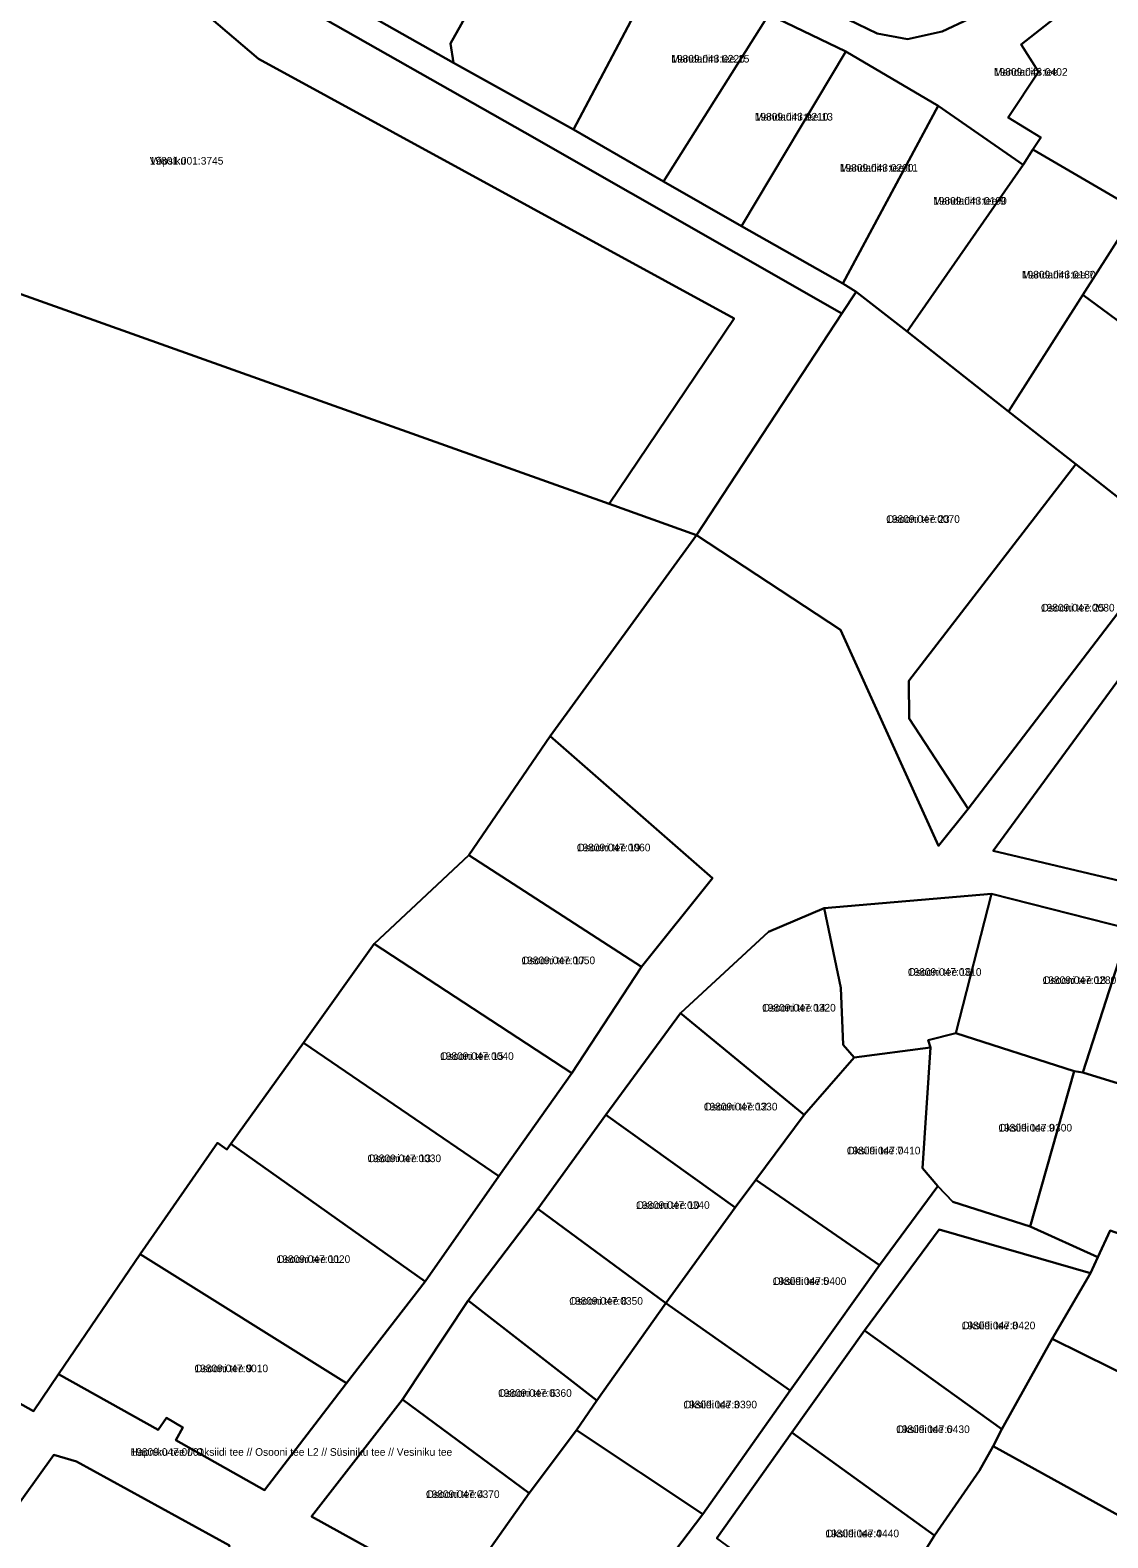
# Model space of a CAD drawing. Extents: x 516875 to 535633, y 6574491 to 6593094.
# Drawn here: x 521809.5 to 522021.7, y 6588097.9 to 6588394.7 of the extents above; entities that cross this region are included whole.
import ezdxf

# ---------------------------------------------------------------- set-up
doc = ezdxf.new("R2010")
doc.units = 0
for name, color, linetype in [('L_AADRESS', 7, 'Continuous'), ('PIIR', 7, 'Continuous'), ('TUNNUS', 7, 'Continuous')]:
    doc.layers.add(name, color=color, linetype=linetype)

msp = doc.modelspace()

# ---------------------------------------------------------------- linework, layer by layer
at = {"layer": 'PIIR'}
for points in [[(521900.47, 6588438.26), (521914.21, 6588425.95), (521901.23, 6588408.16), (521892.23, 6588392.11), (521892.86, 6588388.28), (521865.08, 6588404.07)], [(521767.83, 6588356.93), (521806.88, 6588434.72), (521807.21, 6588435.06), (521811.68, 6588425.58), (521854.43, 6588389.09), (521948.1, 6588337.93), (521923.51, 6588301.46)], [(521976.23, 6588394.06), (521970.55, 6588396.81), (521974.86, 6588399.29), (521966.52, 6588427.38), (521989.2, 6588434.61), (522000.4, 6588405.25), (522000.86, 6588402.21), (521999.67, 6588399.47), (521989.07, 6588394.48), (521982.2, 6588392.97)], [(521892.23, 6588392.11), (521901.23, 6588408.16), (521914.21, 6588425.95), (521934.81, 6588409.94), (521916.48, 6588375.14), (521892.86, 6588388.28)], [(521916.48, 6588375.14), (521934.81, 6588409.94), (521954.92, 6588397.82), (521934.21, 6588364.92)], [(522006.88, 6588371.24), (522008.43, 6588373.57), (522002.04, 6588377.52), (522008, 6588386.5), (522004.6, 6588391.87), (522018.39, 6588402.82), (522044.38, 6588382.1), (522038.94, 6588374.15), (522028.11, 6588358.8), (522027.34, 6588359.31)], [(521934.21, 6588364.92), (521954.92, 6588397.82), (521970.07, 6588390.49), (521949.55, 6588356.12)], [(521969.5, 6588344.88), (521949.55, 6588356.12), (521970.07, 6588390.49), (521988.23, 6588379.85)], [(521969.5, 6588344.88), (521988.23, 6588379.85), (522004.99, 6588368.24), (521982.14, 6588335.38), (521972.13, 6588343.24)], [(521982.14, 6588335.38), (522004.99, 6588368.24), (522006.88, 6588371.24), (522027.34, 6588359.31), (522016.7, 6588342.59), (522002.12, 6588319.68)], [(521662.26, 6588206.2), (521660.34, 6588207.31), (521739.03, 6588351.41), (521745.91, 6588364.74), (521767.83, 6588356.93), (521923.51, 6588301.46), (521940.7, 6588295.34), (521911.84, 6588255.77), (521895.87, 6588232.3), (521877.19, 6588214.89), (521863.3, 6588195.38), (521848.98, 6588175.48), (521848.19, 6588174.37), (521846.41, 6588175.69), (521831.14, 6588153.76), (521815.1, 6588130.16), (521810.15, 6588122.86), (521677.48, 6588197.33)], [(522027.34, 6588359.31), (522028.11, 6588358.8), (522057.37, 6588337.19), (522046.97, 6588320.29), (522016.7, 6588342.59)], [(522015.34, 6588309.29), (521982.46, 6588266.63), (521982.51, 6588259.22), (521994.15, 6588241.44), (521988.31, 6588234.16), (521969.03, 6588276.66), (521940.7, 6588295.34), (521969.29, 6588338.92), (521972.13, 6588343.24), (521982.14, 6588335.38), (522002.12, 6588319.68)], [(522016.7, 6588342.59), (522046.97, 6588320.29), (522041.55, 6588311.63), (522034.49, 6588294.19), (522015.34, 6588309.29), (522002.12, 6588319.68)], [(522034.49, 6588294.19), (521994.15, 6588241.44), (521982.51, 6588259.22), (521982.46, 6588266.63), (522015.34, 6588309.29)], [(522061, 6588274.09), (522025.42, 6588226.93), (521999.1, 6588233.14), (522040.58, 6588289.75)], [(521911.84, 6588255.77), (521943.84, 6588227.81), (521929.82, 6588210.36), (521895.87, 6588232.3)], [(521929.82, 6588210.36), (521916.15, 6588189.39), (521877.19, 6588214.89), (521895.87, 6588232.3)], [(521998.77, 6588224.68), (521991.75, 6588197.28), (521986.29, 6588195.87), (521986.72, 6588194.45), (521971.74, 6588192.49), (521969.57, 6588194.99), (521969.09, 6588206.19), (521965.79, 6588221.88)], [(522025.87, 6588217.8), (522016.71, 6588189.53), (522015.02, 6588189.79), (521991.75, 6588197.28), (521998.77, 6588224.68)], [(521969.09, 6588206.19), (521969.57, 6588194.99), (521971.74, 6588192.49), (521961.88, 6588181.18), (521937.53, 6588201.19), (521954.83, 6588217.23), (521965.79, 6588221.88)], [(522049.87, 6588211.85), (522040.05, 6588182.35), (522037.62, 6588183.1), (522016.71, 6588189.53), (522025.87, 6588217.8)], [(521916.15, 6588189.39), (521901.78, 6588169.12), (521863.3, 6588195.38), (521877.19, 6588214.89)], [(521961.88, 6588181.18), (521952.34, 6588168.38), (521948.3, 6588162.93), (521922.82, 6588181.22), (521937.53, 6588201.19)], [(521991.75, 6588197.28), (522015.02, 6588189.79), (522006.38, 6588159.24), (521991.14, 6588164.07), (521988.17, 6588167.15), (521985.19, 6588170.72), (521986.72, 6588194.45), (521986.29, 6588195.87)], [(521901.78, 6588169.12), (521887.28, 6588148.38), (521848.98, 6588175.48), (521863.3, 6588195.38)], [(521986.72, 6588194.45), (521985.19, 6588170.72), (521988.17, 6588167.15), (521976.69, 6588151.59), (521952.34, 6588168.38), (521961.88, 6588181.18), (521971.74, 6588192.49)], [(522016.71, 6588189.53), (522037.62, 6588183.1), (522028.41, 6588156.16), (522022.09, 6588158.45), (522019.69, 6588153.15), (522006.38, 6588159.24), (522015.02, 6588189.79)], [(521948.3, 6588162.93), (521934.66, 6588144.14), (521909.42, 6588162.67), (521922.82, 6588181.22)], [(521848.19, 6588174.37), (521848.98, 6588175.48), (521887.28, 6588148.38), (521871.78, 6588128.38), (521831.14, 6588153.76), (521846.41, 6588175.69)], [(521976.69, 6588151.59), (521959.11, 6588126.92), (521934.66, 6588144.14), (521948.3, 6588162.93), (521952.34, 6588168.38)], [(521934.66, 6588144.14), (521921.08, 6588124.95), (521895.72, 6588144.67), (521909.42, 6588162.67)], [(522018.22, 6588150), (522010.71, 6588137.12), (522000.79, 6588119.34), (521973.78, 6588138.71), (521988.43, 6588158.61)], [(522028.41, 6588156.16), (522034.11, 6588154.83), (522044.54, 6588150.49), (522061.45, 6588144.69), (522045.71, 6588119.75), (522010.71, 6588137.12), (522018.22, 6588150), (522019.69, 6588153.15), (522022.09, 6588158.45)], [(521871.78, 6588128.38), (521855.66, 6588107.3), (521838.15, 6588117.17), (521839.55, 6588119.64), (521836.37, 6588121.53), (521834.69, 6588119.16), (521815.1, 6588130.16), (521831.14, 6588153.76)], [(521921.08, 6588124.95), (521917.06, 6588119.15), (521907.71, 6588106.69), (521882.77, 6588125.18), (521895.72, 6588144.67)], [(521959.11, 6588126.92), (521941.9, 6588102.55), (521917.06, 6588119.15), (521921.08, 6588124.95), (521934.66, 6588144.14)], [(522000.79, 6588119.34), (521999.11, 6588115.98), (521996.37, 6588111.18), (521987.51, 6588098.39), (521959.43, 6588118.64), (521973.78, 6588138.71)], [(522045.71, 6588119.75), (522030.73, 6588098.49), (521999.11, 6588115.98), (522000.79, 6588119.34), (522010.71, 6588137.12)], [(521907.71, 6588106.69), (521893.34, 6588086.36), (521864.91, 6588102.09), (521882.77, 6588125.18)], [(521941.9, 6588102.55), (521917.98, 6588071.01), (521893.34, 6588086.36), (521907.71, 6588106.69), (521917.06, 6588119.15)], [(521987.51, 6588098.39), (521986.11, 6588096.1), (521972.57, 6588077.42), (521944.66, 6588097.83), (521959.43, 6588118.64)], [(521818.6, 6588112.98), (521848.71, 6588096.4), (521846.75, 6588090.75), (521827.48, 6588065.82), (521796.66, 6588087.52), (521795.86, 6588088.77), (521814.19, 6588114.28)], [(522030.73, 6588098.49), (522015.31, 6588076.21), (521986.11, 6588096.1), (521987.51, 6588098.39), (521996.37, 6588111.18), (521999.11, 6588115.98)]]:
    msp.add_lwpolyline(points, close=True, dxfattribs=at)
for points in [[(521861.27, 6588400.4), (521906.91, 6588374.55), (521969.29, 6588338.92), (521940.7, 6588295.34), (521923.51, 6588301.46), (521948.1, 6588337.93), (521854.43, 6588389.09), (521811.68, 6588425.58)], [(521865.08, 6588404.07), (521892.86, 6588388.28), (521916.48, 6588375.14), (521934.21, 6588364.92), (521949.55, 6588356.12), (521969.5, 6588344.88), (521972.13, 6588343.24), (521969.29, 6588338.92), (521906.91, 6588374.55), (521861.27, 6588400.4)], [(522018.39, 6588402.82), (522004.6, 6588391.87), (522008, 6588386.5), (522002.04, 6588377.52), (522008.43, 6588373.57), (522006.88, 6588371.24), (522004.99, 6588368.24), (521988.23, 6588379.85), (521970.07, 6588390.49), (521954.92, 6588397.82)], [(521970.55, 6588396.81), (521976.23, 6588394.06), (521982.2, 6588392.97), (521989.07, 6588394.48), (521999.67, 6588399.47)], [(521677.48, 6588197.33), (521810.15, 6588122.86), (521815.1, 6588130.16), (521834.69, 6588119.16), (521836.37, 6588121.53), (521839.55, 6588119.64), (521838.15, 6588117.17), (521855.66, 6588107.3), (521871.78, 6588128.38), (521887.28, 6588148.38), (521901.78, 6588169.12), (521916.15, 6588189.39), (521929.82, 6588210.36), (521943.84, 6588227.81), (521911.84, 6588255.77), (521940.7, 6588295.34), (521969.03, 6588276.66), (521988.31, 6588234.16), (521994.15, 6588241.44), (522034.49, 6588294.19)], [(522040.58, 6588289.75), (521999.1, 6588233.14), (522025.42, 6588226.93)], [(522015.31, 6588076.21), (522030.73, 6588098.49), (522045.71, 6588119.75), (522061.45, 6588144.69), (522077.15, 6588170.76), (522081.76, 6588182.84), (522077.96, 6588194.8), (522070.67, 6588204.07), (522049.87, 6588211.85), (522025.87, 6588217.8), (521998.77, 6588224.68), (521965.79, 6588221.88), (521954.83, 6588217.23), (521937.53, 6588201.19), (521922.82, 6588181.22), (521909.42, 6588162.67), (521895.72, 6588144.67), (521882.77, 6588125.18), (521864.91, 6588102.09), (521893.34, 6588086.36)], [(521917.98, 6588071.01), (521941.9, 6588102.55), (521959.11, 6588126.92), (521976.69, 6588151.59), (521988.17, 6588167.15), (521991.14, 6588164.07), (522006.38, 6588159.24), (522019.69, 6588153.15), (522018.22, 6588150), (521988.43, 6588158.61), (521973.78, 6588138.71), (521959.43, 6588118.64), (521944.66, 6588097.83)], [(521848.71, 6588096.4), (521818.6, 6588112.98), (521814.19, 6588114.28), (521795.86, 6588088.77)]]:
    msp.add_lwpolyline(points, dxfattribs=at)

# ---------------------------------------------------------------- texts
at = {"layer": 'L_AADRESS'}
for s, p in [('Mandariini tee 15', (521935.7, 6588388.35)), ('Mandariini tee', (521999.23, 6588385.75)), ('Mandariini tee 13', (521952.14, 6588376.93)), ('Võpsiku', (521833.04, 6588368.26)), ('Mandariini tee 11', (521968.89, 6588366.87)), ('Mandariini tee 9', (521987.25, 6588360.37)), ('Mandariini tee 7', (522004.74, 6588345.84)), ('Osooni tee 23', (521978.02, 6588297.73)), ('Osooni tee 25', (522008.48, 6588280.28)), ('Osooni tee 19', (521917.11, 6588233.07)), ('Osooni tee 17', (521906.22, 6588210.85)), ('Osooni tee 16', (521982.28, 6588208.57)), ('Osooni tee 18', (522008.81, 6588206.96)), ('Osooni tee 14', (521953.59, 6588201.53)), ('Osooni tee 15', (521890.2, 6588192.01)), ('Osooni tee 12', (521942.12, 6588182.06)), ('Oksiidi tee 9', (522000.11, 6588177.91)), ('Osooni tee 13', (521875.9, 6588171.88)), ('Oksiidi tee 7', (521970.26, 6588173.41)), ('Osooni tee 10', (521928.77, 6588162.68)), ('Osooni tee 11', (521858.01, 6588152.04)), ('Oksiidi tee 5', (521955.67, 6588147.71)), ('Osooni tee 8', (521915.63, 6588143.81)), ('Oksiidi tee 8', (521992.88, 6588138.98)), ('Osooni tee 9', (521841.84, 6588130.53)), ('Osooni tee 6', (521901.62, 6588125.68)), ('Oksiidi tee 3', (521938.09, 6588123.41)), ('Oksiidi tee 6', (521979.97, 6588118.55)), ('Hapniku tee // Oksiidi tee // Osooni tee L2 // Süsiniku tee // Vesiniku tee', (521829.26, 6588114.07)), ('Osooni tee 4', (521887.41, 6588105.77)), ('Oksiidi tee 4', (521966.05, 6588098.03))]:
    msp.add_text(s, height=1.5, dxfattribs=at).set_placement(p)
at = {"layer": 'TUNNUS'}
for s, p in [('19809:043:0220', (521935.7, 6588388.35)), ('19809:043:0402', (521999.23, 6588385.75)), ('19809:043:0210', (521952.14, 6588376.93)), ('19801:001:3745', (521833.04, 6588368.26)), ('19809:043:0200', (521968.89, 6588366.87)), ('19809:043:0190', (521987.25, 6588360.37)), ('19809:043:0180', (522004.74, 6588345.84)), ('19809:047:0070', (521978.02, 6588297.73)), ('19809:047:0080', (522008.48, 6588280.28)), ('19809:047:0060', (521917.11, 6588233.07)), ('19809:047:0050', (521906.22, 6588210.85)), ('19809:047:0310', (521982.28, 6588208.57)), ('19809:047:0280', (522008.81, 6588206.96)), ('19809:047:0320', (521953.59, 6588201.53)), ('19809:047:0040', (521890.2, 6588192.01)), ('19809:047:0330', (521942.12, 6588182.06)), ('19809:047:0300', (522000.11, 6588177.91)), ('19809:047:0030', (521875.9, 6588171.88)), ('19809:047:0410', (521970.26, 6588173.41)), ('19809:047:0340', (521928.77, 6588162.68)), ('19809:047:0020', (521858.01, 6588152.04)), ('19809:047:0400', (521955.67, 6588147.71)), ('19809:047:0350', (521915.63, 6588143.81)), ('19809:047:0420', (521992.88, 6588138.98)), ('19809:047:0010', (521841.84, 6588130.53)), ('19809:047:0360', (521901.62, 6588125.68)), ('19809:047:0390', (521938.09, 6588123.41)), ('19809:047:0430', (521979.97, 6588118.55)), ('19809:047:0001', (521829.26, 6588114.07)), ('19809:047:0370', (521887.41, 6588105.77)), ('19809:047:0440', (521966.05, 6588098.03))]:
    msp.add_text(s, height=1.5, dxfattribs=at).set_placement(p)

doc.saveas('drawing.dxf')
